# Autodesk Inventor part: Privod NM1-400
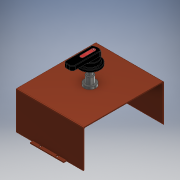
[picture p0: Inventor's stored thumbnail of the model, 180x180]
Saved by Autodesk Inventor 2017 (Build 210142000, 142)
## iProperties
Part Number: Privod NM1-400
Material: Типовые
Document SubType Name: Modeling
Designer: RSagdiev
Density: 1 g/cm^3
Appearance: По умолчанию
Author: RSagdiev
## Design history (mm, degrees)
sketch "Эскиз1"
  geometry: L1 (-37.5, 96.25)-(37.5, 96.25); L2 (37.5, 96.25)-(37.5, 87.75); L3 (37.5, 87.75)-(20.75, 87.75); L4 (-37.5, 87.75)-(-37.5, 96.25); L5 (0, 0)-(119.698, 0); L6 (0, 0)-(-104.809, 0); L7 (0, 94.88)-(0, -60.954); L8 (-20.75, 87.75)-(-16.75, 87.75); L9 (-16.75, 87.75)-(-16.75, 92.75); L10 (-18.75, 94.75)-(-18.75, 94.75); L11 (-20.75, 92.75)-(-20.75, 87.75); L12 (16.75, 87.75)-(16.75, 92.75); L13 (18.75, 94.75)-(18.75, 94.75); L14 (20.75, 87.75)-(16.75, 87.75); L15 (20.75, 92.75)-(20.75, 87.75); L16 (-20.75, 87.75)-(-37.5, 87.75); L17 (-16.75, 87.75)-(-20.75, 87.75); L18 (16.75, 87.75)-(-16.75, 87.75); L19 (20.75, 87.75)-(16.75, 87.75); A1 r 2 centre (-18.75, 92.75) between (-18.75, 94.75) and (-20.75, 92.75); A2 r 2 centre (-18.75, 92.75) between (-16.75, 92.75) and (-18.75, 94.75); A3 r 2 centre (18.75, 92.75) between (18.75, 94.75) and (16.75, 92.75); A4 r 2 centre (18.75, 92.75) between (20.75, 92.75) and (18.75, 94.75); 5 further points
  constraints: 38 end point, 10 point on line, 10 symmetric about line, 8 parallel, 8 point on circle, 4 centre point, 4 horizontal, 4 tangent, 2 perpendicular, 1 concentric, 1 midpoint, 1 vertical, 2 other
  dimensions: "d0" = 87.75 distance between parallel lines of L3 L6 (= 0.5 x Высота); "d1" = 8.5 distance of L1.end L2.end; "d2" = 75 distance between parallel lines of L2 L4 (= 0.5 x Ширина); "d3" = 4 distance of point (-20.75, 94.75) point (-16.75, 94.75); "d4" = 7 distance of point (-16.75, 94.75) L8.end; "d5" = 2 radius of A1 (derived); "d6" = 18.75 distance from line of L4 A1.centre (= 0.25 x d2)
extrude "Выдавливание1" new body sketch "Эскиз1" distance "d7" = 2; taper "d8" = 0 deg
mirror "Зеркальное отражение1"
sketch "Эскиз2"
  geometry: L1 (-37.5, 96.25)-(-37.5, 87.75) reference; L2 (37.5, 87.75)-(37.5, 96.25) reference; L3 (-37.5, -96.25)-(-37.5, -87.75) reference; L4 (37.5, -87.75)-(37.5, -96.25) reference; L5 (-75, 89.75)-(75, 89.75); L6 (75, 89.75)-(75, 87.75); L7 (75, 87.75)-(-75, 87.75); L8 (-75, 87.75)-(-75, 89.75); L9 (-37.5, 87.75)-(-20.75, 87.75) reference
  constraints: 8 end point, 2 parallel, 1 collinear, 1 horizontal, 1 perpendicular
  dimensions: "d13" = 150 distance of L5.start L5.end (= Ширина); "d14" = 2 distance of L5.end L6.end; "d15" = 37.5 distance between parallel lines of L1 L8 (= 0.25 x d13)
extrude "Выдавливание2" join sketch "Эскиз2" distance "d11" = 84 (computed from H1); taper "d12" = 0 deg
mirror "Зеркальное отражение2"
sketch "Эскиз3"
  geometry: L1 (-75, 89.75)-(-37.5, 89.75) reference; L2 (75, -89.75)-(-75, -89.75) reference; L3 (-75, 89.75)-(75, 89.75); L4 (75, 89.75)-(75, -89.75); L5 (75, -89.75)-(-75, -89.75); L6 (-75, -89.75)-(-75, 89.75); 1 further point
  constraints: 8 end point, 2 parallel, 1 horizontal, 1 perpendicular
extrude "Выдавливание3" join sketch "Эскиз3" distance "d16" = 2; taper "d17" = 0 deg
fillet "Сопряжение1" dims "d18" = 2
sketch "Эскиз4"
  geometry: L1 (75, -85.75)-(-75, -85.75) reference; L2 (75, -85.75)-(75, 85.75) reference; L3 (-75, 85.75)-(75, 85.75) reference; L4 (-75, 85.75)-(-75, -85.75) reference; L5 (-75, 85.75)-(-75, -85.75) reference; L6 (-75, -85.75)-(75, 85.75); L7 (75, -85.75)-(75, 85.75) reference; L8 (-75, 85.75)-(75, -85.75); C1 r 5 at (0, 0); 1 further point
  constraints: 4 end point, 1 centre point, 1 coincident
  dimensions: "d19" = 10 diameter of C1
extrude "Выдавливание4" cut sketch "Эскиз4" distance "d20" = 10; taper "d21" = 0 deg
sketch "Эскиз5"
  geometry: C1 r 5 at (0, 0) reference; C2 r 5 at (0, 0); C3 r 8 at (0, 0); 1 further point
  constraints: 2 centre point, 2 coincident
  dimensions: "d22" = 16 diameter of C3
extrude "Выдавливание5" new body sketch "Эскиз5" distance "d23" = 29.33333 (= 0.333333 x H1); taper "d24" = 0 deg
sketch "Эскиз6"
  geometry: C1 r 5 at (0, 0) reference; C2 r 5 at (0, 0); 1 further point
  constraints: 1 centre point, 1 coincident
extrude "Выдавливание6" new body sketch "Эскиз6" distance "d25" = 79.33333 (computed from H1); taper "d26" = 0 deg
sketch "Эскиз7"
  geometry: C1 r 5 at (0, 0) reference; C2 r 13 at (0, 0); C3 r 8 at (0, 0); C4 r 5 at (0, 0); 1 further point
  constraints: 3 centre point, 3 coincident
  dimensions: "d27" = 26 diameter of C2; "d28" = 16 diameter of C3; "d29" = 10 diameter of C4
extrude "Выдавливание7" new body sketch "Эскиз7" distance "d30" = 5; taper "d31" = 0 deg
extrude "Выдавливание8" join sketch "Эскиз7" distance "d32" = 20; taper "d33" = 0 deg
sketch "Эскиз8"
  geometry: C1 r 7 at (0, 0); 1 further point
  constraints: 1 centre point, 1 coincident
  dimensions: "d34" = 14 diameter of C1
extrude "Выдавливание9" new body sketch "Эскиз8" distance "d35" = 3; taper "d36" = 0 deg
fillet "Сопряжение2" dims "d37" = 3
sketch "Эскиз9"
  geometry: L1 (1, 13.17)-(-1, 13.17); L2 (-1, 13.17)-(-1, -13.17); L3 (-1, -13.17)-(1, -13.17); L4 (1, -13.17)-(1, 13.17); L5 (1, 13.17)-(-1, -13.17); L6 (-1, 13.17)-(1, -13.17); L7 (17.109, -1)-(-17.109, -1); L8 (-17.109, -1)-(-17.109, 1); L9 (-17.109, 1)-(17.109, 1); L10 (17.109, 1)-(17.109, -1); L11 (17.109, -1)-(-17.109, 1); L12 (-17.109, -1)-(17.109, 1); C1 r 4 at (0, 0) reference; C2 r 5 at (0, 0) reference; 1 further point
  constraints: 24 end point, 4 midpoint, 4 parallel, 2 horizontal, 2 perpendicular
  dimensions: "d38" = 2 distance of L3.end L2.end; "d39" = 2 distance of L7.end L8.end
extrude "Выдавливание10" cut sketch "Эскиз9" distance "d40" = 1; taper "d41" = 0 deg
sketch "Эскиз10"
  geometry: C1 r 17.5 at (0, 0); A1 r 4 centre (0, 0) between (1, -3.873) and (3.873, -1) reference; 1 further point
  constraints: 1 centre point, 1 coincident
  dimensions: "d42" = 35 diameter of C1
extrude "Выдавливание11" new body sketch "Эскиз10" distance "d43" = 6; taper "d44" = 0 deg; dims "d48" = 3, "d49" = 0
sketch "Эскиз11"
  geometry: C1 r 7 at (0, 0); C2 r 22.5 at (0, 0); 1 further point
  constraints: 2 centre point, 1 coincident
  dimensions: "d45" = 45 diameter of C2
extrude "Выдавливание12" join sketch "Эскиз11" distance "d46" = 6; taper "d47" = 0 deg
sketch "Эскиз12"
  geometry: L1 (-4, -49.361)-(4, -49.361); L2 (10, -43.361)-(10, 10.738); L3 (-10, 10.738)-(-10, -43.361); L4 (-10, -49.361)-(10, 14.361); L5 (10, -49.361)-(-10, 14.361); L6 (-12, 12.738)-(12, 12.738); A1 r 17.5 centre (0, 0) between (10, 14.361) and (0, -17.5) reference; A2 r 17.5 centre (0, 0) between (10, 14.361) and (0, -17.5) reference; A3 r 6 centre (-4, -43.361) between (-10, -43.361) and (-4, -49.361); A4 r 6 centre (4, -43.361) between (4, -49.361) and (10, -43.361); A5 r 2 centre (-12, 10.738) between (-10, 10.738) and (-12, 12.738); A6 r 2 centre (12, 10.738) between (12, 12.738) and (10, 10.738); A7 r 17.5 centre (0, 0) between (12, 12.738) and (-12, 12.738)
  constraints: 16 point on circle, 12 end point, 8 tangent, 6 point on line, 5 centre point, 2 equal radius, 2 horizontal, 2 midpoint, 1 coincident, 1 parallel, 1 perpendicular
  dimensions: "d63" = 20 distance of L4.end L5.end; "d64" = 6 radius of A3; "d66" = 10 distance from line of A1.centre L3; "d67" = 2 radius of A5; "d68" = 2 radius of A6 (derived)
extrude "Выдавливание13" join sketch "Эскиз12" distance "d55" = 10; taper "d56" = 0 deg
fillet "Сопряжение9" dims "d69" = 1
fillet "Сопряжение10" dims "d70" = 1
sketch "Эскиз13"
  geometry: L1 (0, 7.748)-(0, -17.5); L2 (-4, 7.748)-(-4, -17.5); L3 (4, -17.5)-(4, 7.748); A1 r 17.5 centre (0, 0) between (17.5, 0) and (0, -17.5) reference; A2 r 4 centre (0, 7.748) between (4, 7.748) and (-4, 7.748); A3 r 4 centre (0, -17.5) between (-4, -17.5) and (4, -17.5); 2 further points
  constraints: 8 end point, 5 point on circle, 4 tangent, 2 centre point, 1 midpoint, 1 parallel, 1 vertical
  dimensions: "d71" = 8 diameter of A3
extrude "Выдавливание14" cut sketch "Эскиз13" distance "d72" = 0.1; taper "d73" = 0 deg
sketch "Эскиз14"
  geometry: L1 (0, 9.652)-(1.649, 6.796); L2 (1.649, 6.796)-(-1.649, 6.796); L3 (-1.649, 6.796)-(0, 9.652); A1 r 4 centre (0, 7.748) between (4, 7.748) and (-4, 7.748) reference; 2 further points
  constraints: 6 end point, 1 coincident, 7 other
extrude "Выдавливание15" join sketch "Эскиз14" distance "d74" = 0.1; taper "d75" = 0 deg
node "Твердое тело1"
node "Спроецированная петля1"
node "Твердое тело2"
node "Твердое тело3"
node "Твердое тело4"
node "Твердое тело5"
node "Спроецированная петля2"
node "Твердое тело6"
node "Спроецированная петля3"
other parameters: "H1" = 88 [user parameter; used in 3 equation terms], "Высота" = 175.5 [user parameter; used in 1 equation term], "Ширина" = 150 [user parameter; used in 2 equation terms]
